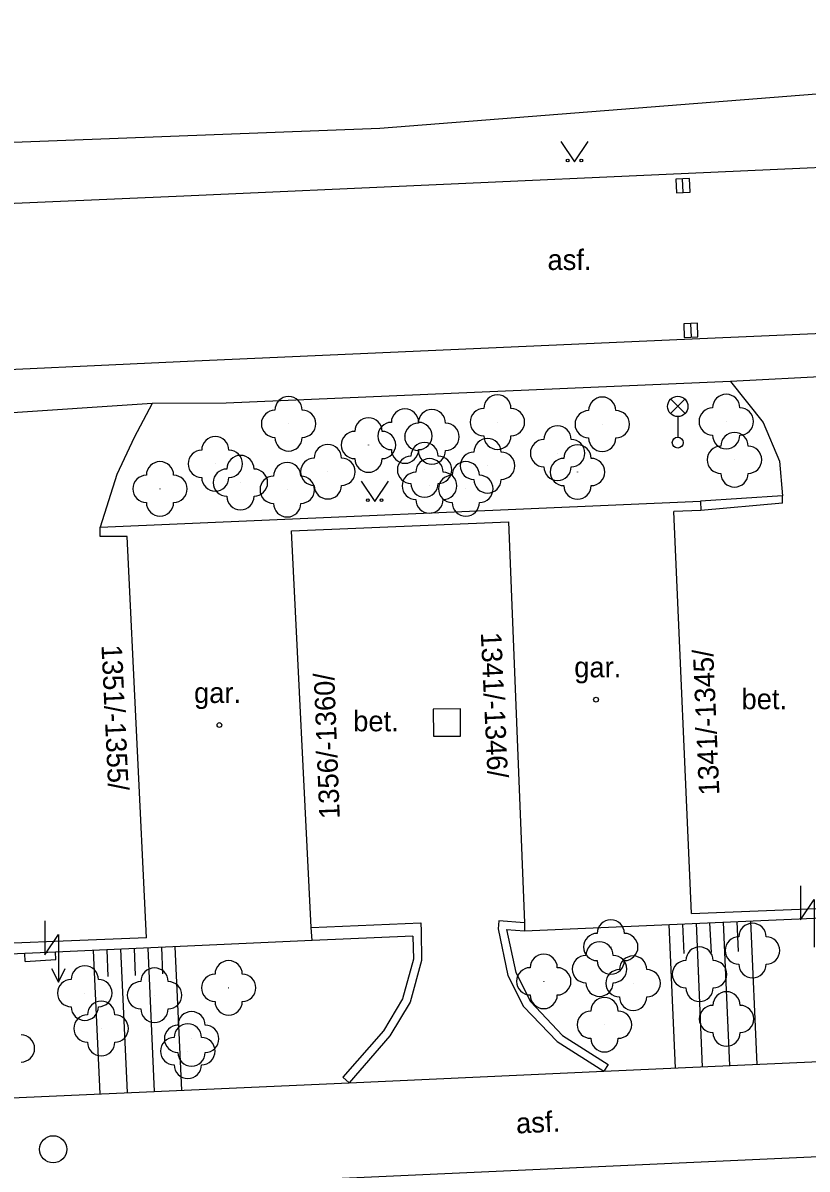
# Model space of a CAD drawing. Extents: x -737812 to -729375, y -1123000 to -1115500.
# Drawn here: x -736531.5 to -736502.72, y -1118226.37 to -1118184.33 of the extents above; entities that cross this region are included whole.
import ezdxf

# ---------------------------------------------------------------- set-up
doc = ezdxf.new("R2010")
doc.units = 0
for name, color, linetype in [('Doplněk polohopisu', 7, 'Continuous'), ('Hranice - ploty_ zdi', 7, 'Continuous'), ('Komunikace', 7, 'Continuous'), ('Pomocné popisy', 7, 'Continuous'), ('Popisy budov', 7, 'Continuous'), ('Povr_ zn_ inž_ sítí - el_', 7, 'Continuous'), ('Povr_ zn_ inž_ sítí - kan_', 7, 'Continuous'), ('Povr_ zn_ inž_ sítí - ner_', 7, 'Continuous'), ('Stavební objekty', 7, 'Continuous'), ('Výškopis', 7, 'Continuous'), ('Zeleň', 7, 'Continuous'), ('Značky druhů budov', 7, 'Continuous'), ('Značky druhů pozemků', 7, 'Continuous'), ('Čísla popisná', 7, 'Continuous')]:
    doc.layers.add(name, color=color, linetype=linetype)

msp = doc.modelspace()

# ---------------------------------------------------------------- linework, layer by layer
at = {"layer": 'Doplněk polohopisu'}
for points in [[(-736505.53, -1118197.48), (-736524.04, -1118198.27), (-736526.76, -1118198.29)], [(-736505.53, -1118197.48), (-736504.34, -1118198.98)], [(-736526.76, -1118198.29), (-736527.42, -1118199.53)], [(-736504.34, -1118198.98), (-736503.74, -1118200.4)], [(-736527.42, -1118199.53), (-736528.05, -1118200.89)], [(-736503.74, -1118200.4), (-736503.63, -1118201.68)], [(-736528.05, -1118200.89), (-736528.67, -1118202.82)]]:
    msp.add_lwpolyline(points, dxfattribs=at)
at = {"layer": 'Hranice - ploty_ zdi'}
for points in [[(-736503.63, -1118201.68), (-736506.64, -1118201.87)], [(-736503.63, -1118201.94), (-736506.63, -1118202.21)], [(-736503.63, -1118201.94), (-736503.63, -1118201.68)], [(-736520.92, -1118217.51), (-736516.9, -1118217.34)], [(-736516.9, -1118217.34), (-736516.89, -1118217.64)], [(-736514.04, -1118217.26), (-736514.06, -1118217.56)], [(-736514.06, -1118217.56), (-736513.7, -1118219.26)], [(-736513.1, -1118217.33), (-736514.04, -1118217.26)], [(-736513.75, -1118217.58), (-736513.09, -1118217.63)], [(-736513.75, -1118217.58), (-736513.41, -1118219.16)], [(-736517.19, -1118217.82), (-736520.88, -1118217.98)], [(-736517.19, -1118217.82), (-736517.17, -1118218.67)], [(-736516.89, -1118217.64), (-736516.87, -1118218.71)], [(-736517.17, -1118218.67), (-736517.57, -1118220.12)], [(-736516.87, -1118218.71), (-736517.29, -1118220.24)], [(-736513.7, -1118219.26), (-736513.13, -1118220.4)], [(-736513.41, -1118219.16), (-736512.88, -1118220.22)], [(-736517.57, -1118220.12), (-736518.27, -1118221.3)], [(-736517.29, -1118220.24), (-736518.03, -1118221.48)], [(-736513.13, -1118220.4), (-736511.89, -1118221.69)], [(-736512.88, -1118220.22), (-736511.7, -1118221.46)], [(-736518.27, -1118221.3), (-736519.76, -1118223)], [(-736518.03, -1118221.48), (-736519.53, -1118223.2)], [(-736511.89, -1118221.69), (-736510.18, -1118222.78)], [(-736511.7, -1118221.46), (-736510.02, -1118222.53)], [(-736510.02, -1118222.53), (-736510.18, -1118222.78)], [(-736519.53, -1118223.2), (-736519.76, -1118223)]]:
    msp.add_lwpolyline(points, dxfattribs=at)
at = {"layer": 'Komunikace'}
for p, q in [((-736498.47, -1118197.12), (-736505.53, -1118197.48)), ((-736526.76, -1118198.29), (-736533.35, -1118198.72))]:
    msp.add_line(p, q, dxfattribs=at)
for points in [[(-736382.94, -1118184.33), (-736394.28, -1118184.84), (-736415.42, -1118185.79), (-736441.35, -1118186.96), (-736469.63, -1118188.21), (-736497.82, -1118189.44), (-736525.6, -1118190.68), (-736553.59, -1118191.9), (-736582.16, -1118193.13)], [(-736581.67, -1118199.22), (-736563.35, -1118198.45), (-736553.37, -1118198), (-736535.19, -1118197.19), (-736525.2, -1118196.72), (-736507.22, -1118195.93), (-736497.34, -1118195.5), (-736479.37, -1118194.7), (-736469.37, -1118194.25), (-736451.41, -1118193.48), (-736441.43, -1118193.02), (-736418.32, -1118192.01), (-736415.33, -1118192.1), (-736413.62, -1118192.35), (-736411.05, -1118193)], [(-736510.18, -1118222.78), (-736493.01, -1118222.01)], [(-736519.53, -1118223.2), (-736510.18, -1118222.78)], [(-736537.98, -1118224.02), (-736519.53, -1118223.2)], [(-736500.96, -1118225.85), (-736521.67, -1118226.8)]]:
    msp.add_lwpolyline(points, dxfattribs=at)
at = {"layer": 'Povr_ zn_ inž_ sítí - el_'}
for p, q in [((-736507.734, -1118198.658), (-736507.206, -1118198.13)), ((-736507.198, -1118198.655), (-736507.726, -1118198.126)), ((-736507.47, -1118198.77), (-736507.47, -1118199.52))]:
    msp.add_line(p, q, dxfattribs=at)
for points in [[(-736502.97, -1118215.98), (-736502.97, -1118217.23), (-736502.47, -1118216.48), (-736502.47, -1118218.23)], [(-736530.7, -1118217.26), (-736530.7, -1118218.51), (-736530.2, -1118217.76), (-736530.2, -1118219.51)], [(-736530.45, -1118219.01), (-736530.2, -1118219.51), (-736529.95, -1118219.01)]]:
    msp.add_lwpolyline(points, dxfattribs=at)
for centre, radius in [((-736507.47, -1118198.395), 0.375), ((-736507.47, -1118199.72), 0.2)]:
    msp.add_circle(centre, radius, dxfattribs=at)
at = {"layer": 'Povr_ zn_ inž_ sítí - kan_'}
for p, q in [((-736507.269, -1118190.55), (-736507.291, -1118190.05)), ((-736507.001, -1118195.35), (-736506.979, -1118195.85))]:
    msp.add_line(p, q, dxfattribs=at)
for points in [[(-736507.018, -1118190.539), (-736507.04, -1118190.039), (-736507.541, -1118190.061), (-736507.519, -1118190.561)], [(-736507.252, -1118195.361), (-736507.23, -1118195.861), (-736506.729, -1118195.839), (-736506.751, -1118195.339)]]:
    msp.add_lwpolyline(points, close=True, dxfattribs=at)
msp.add_circle((-736530.39, -1118225.64), 0.5, dxfattribs=at)
at = {"layer": 'Povr_ zn_ inž_ sítí - ner_'}
for p, q in [((-736515.443, -1118209.487), (-736516.443, -1118209.493)), ((-736516.443, -1118209.493), (-736516.437, -1118210.493)), ((-736515.437, -1118210.487), (-736515.443, -1118209.487)), ((-736516.437, -1118210.493), (-736515.437, -1118210.487))]:
    msp.add_line(p, q, dxfattribs=at)
at = {"layer": 'Stavební objekty'}
for points in [[(-736528.67, -1118202.82), (-736506.64, -1118201.87)], [(-736506.64, -1118201.87), (-736506.63, -1118202.21)], [(-736506.63, -1118202.21), (-736507.61, -1118202.25)], [(-736506.97, -1118216.99), (-736507.61, -1118202.25)], [(-736528.67, -1118203.16), (-736528.67, -1118202.82)], [(-736521.64, -1118202.96), (-736513.68, -1118202.63)], [(-736513.68, -1118202.63), (-736513.1, -1118217.33), (-736513.09, -1118217.63)], [(-736527.67, -1118203.17), (-736528.67, -1118203.16)], [(-736526.97, -1118217.89), (-736527.67, -1118203.17)], [(-736520.88, -1118217.98), (-736520.92, -1118217.51), (-736521.64, -1118202.96)], [(-736513.09, -1118217.63), (-736503.58, -1118217.21), (-736502.46, -1118217.16), (-736493.02, -1118216.75)], [(-736506.97, -1118216.99), (-736499.03, -1118216.68)], [(-736520.88, -1118217.98), (-736530.3, -1118218.41), (-736531.43, -1118218.46), (-736541.02, -1118218.9)], [(-736526.97, -1118217.89), (-736534.92, -1118218.2)], [(-736530.29, -1118218.68), (-736530.3, -1118218.41)], [(-736531.42, -1118218.75), (-736531.43, -1118218.46)], [(-736531.42, -1118218.75), (-736530.29, -1118218.68)]]:
    msp.add_lwpolyline(points, dxfattribs=at)
at = {"layer": 'Výškopis'}
for points in [[(-736507.8, -1118217.4), (-736507.57, -1118222.66)], [(-736507.3, -1118217.38), (-736507.25, -1118218.46)], [(-736506.8, -1118217.35), (-736506.57, -1118222.62)], [(-736506.3, -1118217.33), (-736506.25, -1118218.42)], [(-736505.8, -1118217.31), (-736505.57, -1118222.57)], [(-736505.3, -1118217.29), (-736505.25, -1118218.38)], [(-736504.8, -1118217.27), (-736504.57, -1118222.53)], [(-736528.92, -1118218.35), (-736528.68, -1118223.61)], [(-736528.42, -1118218.32), (-736528.38, -1118219.3)], [(-736527.92, -1118218.3), (-736527.68, -1118223.56)], [(-736527.42, -1118218.28), (-736527.38, -1118219.26)], [(-736526.92, -1118218.26), (-736526.68, -1118223.52)], [(-736526.42, -1118218.23), (-736526.38, -1118219.21)], [(-736525.93, -1118218.21), (-736525.68, -1118223.47)]]:
    msp.add_lwpolyline(points, dxfattribs=at)
at = {"layer": 'Zeleň'}
for points in [[(-736518.4, -1118188.19), (-736502.38, -1118186.93)], [(-736537.94, -1118188.93), (-736518.4, -1118188.19)]]:
    msp.add_lwpolyline(points, dxfattribs=at)
for centre in [(-736521.75, -1118199.03), (-736514.09, -1118198.97), (-736510.24, -1118199.05), (-736505.69, -1118198.95), (-736517.48, -1118199.48), (-736516.49, -1118199.51), (-736518.82, -1118199.81), (-736511.88, -1118200.11), (-736505.39, -1118200.35), (-736524.44, -1118200.5), (-736516.76, -1118200.72), (-736514.45, -1118200.57), (-736523.52, -1118201.19), (-736520.31, -1118200.79), (-736511.15, -1118200.8), (-736526.47, -1118201.42), (-736521.8, -1118201.45), (-736516.58, -1118201.31), (-736515.25, -1118201.42), (-736509.93, -1118218.22), (-736504.73, -1118218.35), (-736510.34, -1118219.03), (-736506.67, -1118219.22), (-736512.39, -1118219.48), (-736509.11, -1118219.55), (-736529.23, -1118219.91), (-736526.67, -1118219.99), (-736523.95, -1118219.72), (-736505.68, -1118220.86), (-736528.63, -1118221.21), (-736510.16, -1118221.07), (-736525.31, -1118221.59), (-736525.45, -1118222.04)]:
    msp.add_circle(centre, 0.0005, dxfattribs=at)
for centre, start, end in [((-736521.75, -1118198.53), 360, 180), ((-736514.09, -1118198.47), 360, 180), ((-736510.24, -1118198.55), 360, 180), ((-736505.69, -1118198.45), 360, 180), ((-736522.25, -1118199.03), 90, 270), ((-736521.25, -1118199.03), 270, 90), ((-736517.48, -1118198.98), 360, 180), ((-736516.49, -1118199.01), 360, 180), ((-736514.59, -1118198.97), 90, 270), ((-736513.59, -1118198.97), 270, 90), ((-736510.74, -1118199.05), 90, 270), ((-736509.74, -1118199.05), 270, 90), ((-736506.19, -1118198.95), 90, 270), ((-736505.19, -1118198.95), 270, 90), ((-736518.82, -1118199.31), 360, 180), ((-736517.98, -1118199.48), 90, 270), ((-736516.99, -1118199.51), 90, 270), ((-736516.98, -1118199.48), 270, 90), ((-736515.99, -1118199.51), 270, 90), ((-736524.44, -1118200), 360, 180), ((-736519.32, -1118199.81), 90, 270), ((-736518.32, -1118199.81), 270, 90), ((-736514.09, -1118199.47), 180, 360), ((-736511.88, -1118199.61), 360, 180), ((-736505.69, -1118199.45), 180, 360), ((-736505.39, -1118199.85), 360, 180), ((-736521.75, -1118199.53), 180, 360), ((-736520.31, -1118200.29), 360, 180), ((-736516.76, -1118200.22), 360, 180), ((-736514.45, -1118200.07), 360, 180), ((-736512.38, -1118200.11), 90, 270), ((-736511.15, -1118200.3), 360, 180), ((-736511.38, -1118200.11), 270, 90), ((-736510.24, -1118199.55), 180, 360), ((-736505.89, -1118200.35), 90, 270), ((-736504.89, -1118200.35), 270, 90), ((-736524.94, -1118200.5), 90, 270), ((-736523.52, -1118200.69), 360, 180), ((-736523.94, -1118200.5), 270, 90), ((-736520.81, -1118200.79), 90, 270), ((-736519.81, -1118200.79), 270, 90), ((-736518.82, -1118200.31), 180, 360), ((-736517.48, -1118199.98), 180, 360), ((-736517.26, -1118200.72), 90, 270), ((-736516.58, -1118200.81), 360, 180), ((-736516.49, -1118200.01), 180, 360), ((-736516.26, -1118200.72), 270, 90), ((-736514.95, -1118200.57), 90, 270), ((-736513.95, -1118200.57), 270, 90), ((-736511.65, -1118200.8), 90, 270), ((-736510.65, -1118200.8), 270, 90), ((-736526.47, -1118200.92), 360, 180), ((-736524.02, -1118201.19), 90, 270), ((-736523.02, -1118201.19), 270, 90), ((-736521.8, -1118200.95), 360, 180), ((-736515.25, -1118200.92), 360, 180), ((-736511.88, -1118200.61), 180, 360), ((-736526.97, -1118201.42), 90, 270), ((-736525.97, -1118201.42), 270, 90), ((-736524.44, -1118201), 180, 360), ((-736522.3, -1118201.45), 90, 270), ((-736521.3, -1118201.45), 270, 90), ((-736517.08, -1118201.31), 90, 270), ((-736515.75, -1118201.42), 90, 270), ((-736516.08, -1118201.31), 270, 90), ((-736514.45, -1118201.07), 180, 360), ((-736514.75, -1118201.42), 270, 90), ((-736505.39, -1118200.85), 180, 360), ((-736520.31, -1118201.29), 180, 360), ((-736516.76, -1118201.22), 180, 360), ((-736511.15, -1118201.3), 180, 360), ((-736526.47, -1118201.92), 180, 360), ((-736523.52, -1118201.69), 180, 360), ((-736521.8, -1118201.95), 180, 360), ((-736516.58, -1118201.81), 180, 360), ((-736515.25, -1118201.92), 180, 360), ((-736509.93, -1118217.72), 360, 180), ((-736504.73, -1118217.85), 360, 180), ((-736510.43, -1118218.22), 90, 270), ((-736509.43, -1118218.22), 270, 90), ((-736505.23, -1118218.35), 90, 270), ((-736504.23, -1118218.35), 270, 90), ((-736510.34, -1118218.53), 360, 180), ((-736506.67, -1118218.72), 360, 180), ((-736523.95, -1118219.22), 360, 180), ((-736512.39, -1118218.98), 360, 180), ((-736510.84, -1118219.03), 90, 270), ((-736509.93, -1118218.72), 180, 360), ((-736509.84, -1118219.03), 270, 90), ((-736509.11, -1118219.05), 360, 180), ((-736507.17, -1118219.22), 90, 270), ((-736506.17, -1118219.22), 270, 90), ((-736504.73, -1118218.85), 180, 360), ((-736529.23, -1118219.41), 360, 180), ((-736526.67, -1118219.49), 360, 180), ((-736524.45, -1118219.72), 90, 270), ((-736523.45, -1118219.72), 270, 90), ((-736512.89, -1118219.48), 90, 270), ((-736511.89, -1118219.48), 270, 90), ((-736509.61, -1118219.55), 90, 270), ((-736508.61, -1118219.55), 270, 90), ((-736529.73, -1118219.91), 90, 270), ((-736528.73, -1118219.91), 270, 90), ((-736527.17, -1118219.99), 90, 270), ((-736526.17, -1118219.99), 270, 90), ((-736510.34, -1118219.53), 180, 360), ((-736512.39, -1118219.98), 180, 360), ((-736510.16, -1118220.57), 360, 180), ((-736509.11, -1118220.05), 180, 360), ((-736506.67, -1118219.72), 180, 360), ((-736505.68, -1118220.36), 360, 180), ((-736529.23, -1118220.41), 180, 360), ((-736528.63, -1118220.71), 360, 180), ((-736526.67, -1118220.49), 180, 360), ((-736523.95, -1118220.22), 180, 360), ((-736506.18, -1118220.86), 90, 270), ((-736505.18, -1118220.86), 270, 90), ((-736529.13, -1118221.21), 90, 270), ((-736528.13, -1118221.21), 270, 90), ((-736525.31, -1118221.09), 360, 180), ((-736510.66, -1118221.07), 90, 270), ((-736509.66, -1118221.07), 270, 90), ((-736525.81, -1118221.59), 90, 270), ((-736525.45, -1118221.54), 360, 180), ((-736524.81, -1118221.59), 270, 90), ((-736505.68, -1118221.36), 180, 360), ((-736531.57, -1118221.94), 270, 90), ((-736528.63, -1118221.71), 180, 360), ((-736525.95, -1118222.04), 90, 270), ((-736524.95, -1118222.04), 270, 90), ((-736510.16, -1118221.57), 180, 360), ((-736525.31, -1118222.09), 180, 360), ((-736525.45, -1118222.54), 180, 360)]:
    msp.add_arc(centre, 0.5, start, end, dxfattribs=at)
at = {"layer": 'Značky druhů budov'}
for centre in [(-736510.47, -1118209.15), (-736524.29, -1118210.08)]:
    msp.add_circle(centre, 0.0875, dxfattribs=at)
at = {"layer": 'Značky druhů pozemků'}
for points in [[(-736511.76, -1118188.68), (-736511.26, -1118189.43), (-736510.76, -1118188.68)], [(-736519.09, -1118201.13), (-736518.59, -1118201.88), (-736518.09, -1118201.13)]]:
    msp.add_lwpolyline(points, dxfattribs=at)
for centre in [(-736511.51, -1118189.38), (-736511.01, -1118189.38), (-736518.84, -1118201.83), (-736518.34, -1118201.83)]:
    msp.add_circle(centre, 0.05, dxfattribs=at)

# ---------------------------------------------------------------- texts
at = {"layer": 'Pomocné popisy'}
for s, p in [('asf.', (-736512.25, -1118193.39)), ('bet.', (-736505.13, -1118209.5)), ('bet.', (-736519.38, -1118210.31))]:
    msp.add_text(s, height=0.75, dxfattribs=at).set_placement(p)
msp.add_text('asf.', height=0.75, rotation=2.5896, dxfattribs=at).set_placement((-736513.39, -1118225.06))
at = {"layer": 'Popisy budov'}
for p in [(-736511.27, -1118208.33), (-736525.22, -1118209.27)]:
    msp.add_text('gar.', height=0.75, dxfattribs=at).set_placement(p)
at = {"layer": 'Čísla popisná'}
for s, rotation, p in [('1341/-1346/', 272.7226, (-736514.7, -1118206.69)), ('1351/-1355/', 272.7226, (-736528.62, -1118207.15)), ('1341/-1345/', 92.4692, (-736505.94, -1118212.64)), ('1356/-1360/', 92.2525, (-736519.87, -1118213.51))]:
    msp.add_text(s, height=0.75, rotation=rotation, dxfattribs=at).set_placement(p)

doc.saveas('drawing.dxf')
